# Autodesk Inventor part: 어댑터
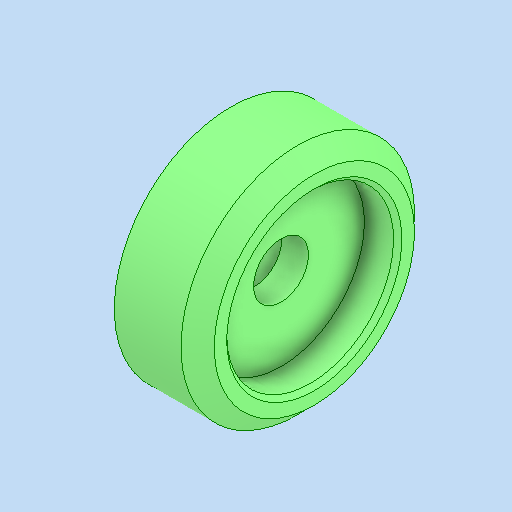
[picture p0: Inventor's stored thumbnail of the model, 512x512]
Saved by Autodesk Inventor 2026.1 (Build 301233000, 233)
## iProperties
Created: 2025-09
Part Number: 어댑터
Material: 강철, 탄소
Document SubType Name: Modeling
Designer: PC-30
Density: 7.85 g/cm^3
Appearance: 기본값
Author: jhkim
Sending System: Autodesk Inventor 2026
Preprocessor: ST-DEVELOPER v20.1
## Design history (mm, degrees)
feature "솔리드1"
node "솔리드2"
